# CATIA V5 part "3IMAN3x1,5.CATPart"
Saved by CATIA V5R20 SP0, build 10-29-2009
Part number: 3IMAN3x1,5
Revision: ANY
Definition: UNKNOWN
Nomenclature: 3IMAN3x1,5
Source: Unknown
Bounding box of the stored display mesh (mm): x -1.5 to 1.5, y -1.5 to 1.5, z 0 to 1.5
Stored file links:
  C:\Users\Utente\Desktop\IO LAVORO\3D X SITO CF\CUMSA\3D files SX.256062\SX 256062\3IMAN3x1,5.CATPart
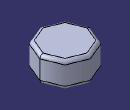
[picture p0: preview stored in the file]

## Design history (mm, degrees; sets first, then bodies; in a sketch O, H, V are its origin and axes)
Body1 "Redondeo1" (main body)
  Solid1: solid without history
